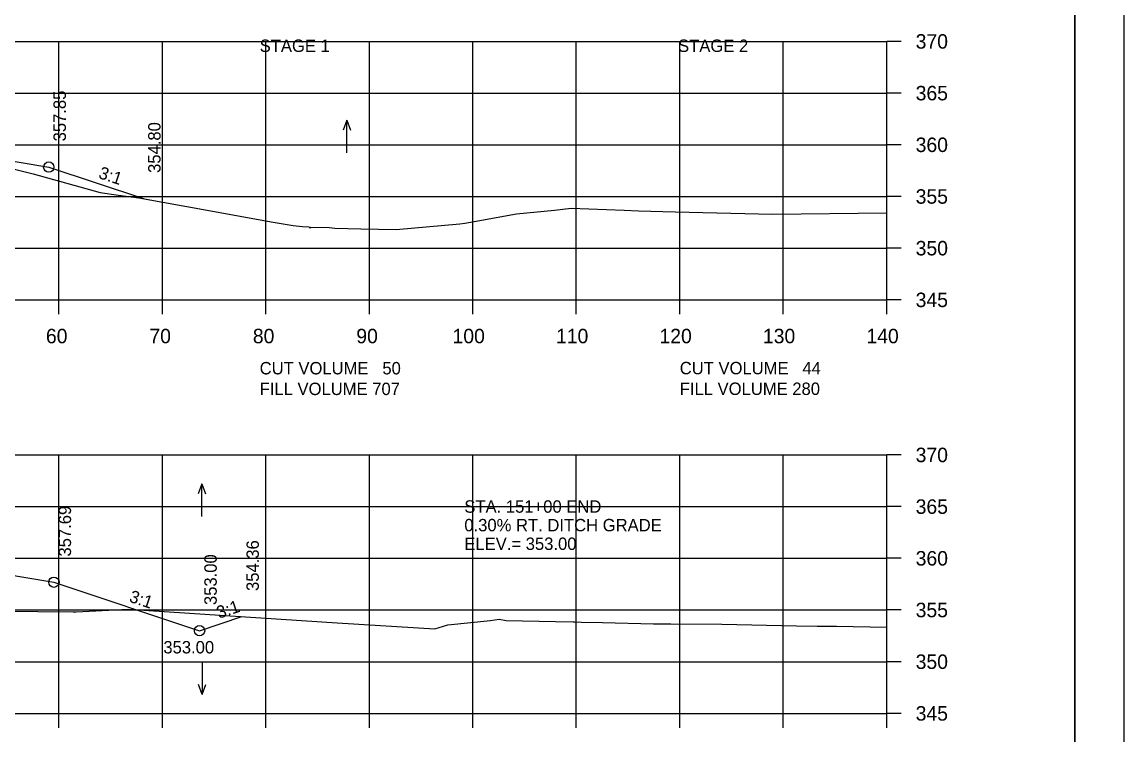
# Model space of a CAD drawing. Extents: x 1374859 to 1376773, y 382242 to 389804.
# Drawn here: x 1376191 to 1376297.5, y 386606.4 to 386675.4 of the extents above; entities that cross this region are included whole.
import ezdxf

# ---------------------------------------------------------------- set-up
doc = ezdxf.new("R2010")
doc.units = 0
for name, color, linetype in [('R_Axis', 7, 'Continuous'), ('R_Axis Annot', 7, 'Continuous'), ('R_Border', 7, 'Continuous'), ('R_Detour Annot', 7, 'Continuous'), ('R_Exist Surface', 7, 'Continuous'), ('R_Fin Surface', 7, 'Continuous'), ('R_Grid', 7, 'Continuous'), ('R_No Plot', 7, 'Continuous'), ('R_Water Annot', 7, 'Continuous'), ('R_Xsect Elev', 7, 'Continuous'), ('R_Xsect Slope', 7, 'Continuous')]:
    doc.layers.add(name, color=color, linetype=linetype)

msp = doc.modelspace()

# ---------------------------------------------------------------- linework, layer by layer
at = {"layer": 'R_Axis'}
for p, q in [((1376274.57, 386648.48), (1376274.57, 386673.48)), ((1376275.97, 386673.48), (1376274.57, 386673.48)), ((1376275.97, 386668.48), (1376274.57, 386668.48)), ((1376275.97, 386663.48), (1376274.57, 386663.48)), ((1376275.97, 386658.48), (1376274.57, 386658.48)), ((1376275.97, 386653.48), (1376274.57, 386653.48)), ((1375994.57, 386648.48), (1376274.57, 386648.48)), ((1376194.57, 386647.08), (1376194.57, 386648.48)), ((1376204.57, 386647.08), (1376204.57, 386648.48)), ((1376214.57, 386647.08), (1376214.57, 386648.48)), ((1376224.57, 386647.08), (1376224.57, 386648.48)), ((1376234.57, 386647.08), (1376234.57, 386648.48)), ((1376244.57, 386647.08), (1376244.57, 386648.48)), ((1376254.57, 386647.08), (1376254.57, 386648.48)), ((1376264.57, 386647.08), (1376264.57, 386648.48)), ((1376274.57, 386647.08), (1376274.57, 386648.48)), ((1376275.97, 386648.48), (1376274.57, 386648.48)), ((1376274.57, 386608.48), (1376274.57, 386633.48)), ((1376275.97, 386633.48), (1376274.57, 386633.48)), ((1376275.97, 386628.48), (1376274.57, 386628.48)), ((1376275.97, 386623.48), (1376274.57, 386623.48)), ((1376275.97, 386618.48), (1376274.57, 386618.48)), ((1376275.97, 386613.48), (1376274.57, 386613.48)), ((1375994.57, 386608.48), (1376274.57, 386608.48)), ((1376194.57, 386607.08), (1376194.57, 386608.48)), ((1376204.57, 386607.08), (1376204.57, 386608.48)), ((1376214.57, 386607.08), (1376214.57, 386608.48)), ((1376224.57, 386607.08), (1376224.57, 386608.48)), ((1376234.57, 386607.08), (1376234.57, 386608.48)), ((1376244.57, 386607.08), (1376244.57, 386608.48)), ((1376254.57, 386607.08), (1376254.57, 386608.48)), ((1376264.57, 386607.08), (1376264.57, 386608.48)), ((1376274.57, 386607.08), (1376274.57, 386608.48)), ((1376275.97, 386608.48), (1376274.57, 386608.48))]:
    msp.add_line(p, q, dxfattribs=at)
at = {"layer": 'R_Border'}
msp.add_line((1376292.75, 386512.48), (1376292.75, 386717.94), dxfattribs=at)
at = {"layer": 'R_Exist Surface'}
for points in [[(1376190.27, 386661.12), (1376192.09, 386660.68), (1376198.56, 386658.87), (1376200.32, 386658.61), (1376202.29, 386658.36), (1376209.25, 386657.09), (1376215.09, 386656.03), (1376217.22, 386655.66), (1376218.1, 386655.56), (1376218.71, 386655.53), (1376218.84, 386655.43), (1376218.93, 386655.52), (1376220.72, 386655.47), (1376221.23, 386655.4), (1376223.74, 386655.34), (1376227.16, 386655.28), (1376233.31, 386655.84), (1376233.8, 386655.89), (1376234.34, 386655.99), (1376238.78, 386656.8), (1376242.46, 386657.17), (1376244.07, 386657.34), (1376249.19, 386657.17), (1376250.58, 386657.1), (1376254.12, 386657.01), (1376263.54, 386656.76), (1376274.57, 386656.91)], [(1376189.12, 386618.37), (1376195.93, 386618.29), (1376196.15, 386618.29), (1376196.2, 386618.29), (1376196.21, 386618.29), (1376196.21, 386618.3), (1376196.22, 386618.3), (1376201.3, 386618.56), (1376221.45, 386617.23), (1376230.9, 386616.66), (1376232.16, 386617.03), (1376236.29, 386617.45), (1376237.13, 386617.6), (1376237.8, 386617.48), (1376242.55, 386617.37), (1376244.28, 386617.33), (1376244.41, 386617.35), (1376245.07, 386617.31), (1376247.09, 386617.27), (1376252.03, 386617.13), (1376253.72, 386617.15), (1376258.63, 386617.11), (1376265.84, 386616.95), (1376267.85, 386616.93), (1376269.73, 386616.92), (1376274.57, 386616.82)]]:
    msp.add_lwpolyline(points, dxfattribs=at)
at = {"layer": 'R_Fin Surface'}
for points in [[(1376053.96, 386656.68), (1376057.81, 386655.4), (1376075.59, 386661.33), (1376090.15, 386663.76), (1376097.59, 386665), (1376105.59, 386665.32), (1376134.59, 386665.9), (1376163.59, 386665.32), (1376171.59, 386665), (1376179.02, 386663.76), (1376193.59, 386661.33), (1376202.74, 386658.28)], [(1376052.47, 386616.79), (1376057.21, 386615.21), (1376075.09, 386621.17), (1376089.65, 386623.6), (1376097.09, 386624.84), (1376105.09, 386625.16), (1376134.59, 386625.75), (1376164.09, 386625.16), (1376172.09, 386624.84), (1376179.52, 386623.6), (1376194.09, 386621.17), (1376208.16, 386616.48), (1376212.24, 386617.84)]]:
    msp.add_lwpolyline(points, dxfattribs=at)
at = {"layer": 'R_Grid'}
for p, q in [((1375994.57, 386673.48), (1376274.57, 386673.48)), ((1376194.57, 386648.48), (1376194.57, 386673.48)), ((1376204.57, 386648.48), (1376204.57, 386673.48)), ((1376214.57, 386648.48), (1376214.57, 386673.48)), ((1376224.57, 386648.48), (1376224.57, 386673.48)), ((1376234.57, 386648.48), (1376234.57, 386673.48)), ((1376244.57, 386648.48), (1376244.57, 386673.48)), ((1376254.57, 386648.48), (1376254.57, 386673.48)), ((1376264.57, 386648.48), (1376264.57, 386673.48)), ((1376274.57, 386648.48), (1376274.57, 386673.48)), ((1375994.57, 386668.48), (1376274.57, 386668.48)), ((1375994.57, 386663.48), (1376274.57, 386663.48)), ((1375994.57, 386658.48), (1376274.57, 386658.48)), ((1375994.57, 386653.48), (1376274.57, 386653.48)), ((1375994.57, 386648.48), (1376274.57, 386648.48)), ((1375994.57, 386633.48), (1376274.57, 386633.48)), ((1376194.57, 386608.48), (1376194.57, 386633.48)), ((1376204.57, 386608.48), (1376204.57, 386633.48)), ((1376214.57, 386608.48), (1376214.57, 386633.48)), ((1376224.57, 386608.48), (1376224.57, 386633.48)), ((1376234.57, 386608.48), (1376234.57, 386633.48)), ((1376244.57, 386608.48), (1376244.57, 386633.48)), ((1376254.57, 386608.48), (1376254.57, 386633.48)), ((1376264.57, 386608.48), (1376264.57, 386633.48)), ((1376274.57, 386608.48), (1376274.57, 386633.48)), ((1375994.57, 386628.48), (1376274.57, 386628.48)), ((1375994.57, 386623.48), (1376274.57, 386623.48)), ((1375994.57, 386618.48), (1376274.57, 386618.48)), ((1375994.57, 386613.48), (1376274.57, 386613.48)), ((1375994.57, 386608.48), (1376274.57, 386608.48))]:
    msp.add_line(p, q, dxfattribs=at)
at = {"layer": 'R_No Plot'}
for points in [[(1375964.16, 386721.83), (1376297.5, 386721.83), (1376297.5, 386508.5), (1375964.16, 386508.5)], [(1376210.49, 386717.94), (1376210.49, 386708.06), (1376246.22, 386708.06), (1376246.22, 386705.14), (1376269.42, 386705.14), (1376269.42, 386680.81), (1376292.75, 386680.81), (1376292.75, 386512.48), (1375976.57, 386512.48), (1375976.57, 386717.94)]]:
    msp.add_lwpolyline(points, close=True, dxfattribs=at)
for centre in [(1376193.59, 386661.33), (1376194.09, 386621.17), (1376208.16, 386616.48)]:
    msp.add_circle(centre, 0.5, dxfattribs=at)
at = {"layer": 'R_Water Annot'}
for p, q in [((1376222.4, 386665.85), (1376222.05, 386664.89)), ((1376222.4, 386662.71), (1376222.4, 386665.85)), ((1376222.4, 386665.85), (1376222.75, 386664.89)), ((1376208.37, 386630.68), (1376208.02, 386629.72)), ((1376208.37, 386627.54), (1376208.37, 386630.68)), ((1376208.37, 386630.68), (1376208.72, 386629.72)), ((1376208.42, 386613.45), (1376208.42, 386610.31)), ((1376208.42, 386610.31), (1376208.07, 386611.27)), ((1376208.42, 386610.31), (1376208.77, 386611.27))]:
    msp.add_line(p, q, dxfattribs=at)

# ---------------------------------------------------------------- texts
at = {"layer": 'R_Axis Annot'}
for s, p in [('STAGE 1', (1376213.97, 386672.46)), ('STAGE 2', (1376254.41, 386672.46))]:
    msp.add_text(s, height=1.2, rotation=360, dxfattribs=at).set_placement(p)
for s, height, p in [('370', 1.4, (1376277.37, 386672.78)), ('365', 1.4, (1376277.37, 386667.78)), ('360', 1.4, (1376277.37, 386662.78)), ('355', 1.4, (1376277.37, 386657.78)), ('350', 1.4, (1376277.37, 386652.78)), ('345', 1.4, (1376277.37, 386647.78)), ('60', 1.4, (1376193.31, 386644.28)), ('70', 1.4, (1376203.31, 386644.28)), ('80', 1.4, (1376213.31, 386644.28)), ('90', 1.4, (1376223.31, 386644.28)), ('100', 1.4, (1376232.61, 386644.28)), ('110', 1.4, (1376242.61, 386644.28)), ('120', 1.4, (1376252.61, 386644.28)), ('130', 1.4, (1376262.61, 386644.28)), ('140', 1.4, (1376272.61, 386644.28)), ('CUT VOLUME   50', 1.2, (1376213.97, 386641.27)), ('CUT VOLUME   44', 1.2, (1376254.57, 386641.28)), ('FILL VOLUME 707', 1.2, (1376213.97, 386639.27)), ('FILL VOLUME 280', 1.2, (1376254.57, 386639.28)), ('370', 1.4, (1376277.37, 386632.78)), ('365', 1.4, (1376277.37, 386627.78)), ('360', 1.4, (1376277.37, 386622.78)), ('355', 1.4, (1376277.37, 386617.78)), ('350', 1.4, (1376277.37, 386612.78)), ('345', 1.4, (1376277.37, 386607.78))]:
    msp.add_text(s, height=height, dxfattribs=at).set_placement(p)
at = {"layer": 'R_Detour Annot'}
for s, p in [('STA. 151+00 END', (1376233.75, 386627.89)), ('0.30% RT. DITCH GRADE', (1376233.75, 386626.09)), ('ELEV.= 353.00', (1376233.75, 386624.29))]:
    msp.add_text(s, height=1.2, dxfattribs=at).set_placement(p)
at = {"layer": 'R_Xsect Elev'}
for s, p in [('357.85', (1376195.24, 386663.81)), ('354.80', (1376204.39, 386660.76)), ('357.69', (1376195.74, 386623.65)), ('354.36', (1376213.89, 386620.32)), ('353.00', (1376209.82, 386618.96))]:
    msp.add_text(s, height=1.2, rotation=90, dxfattribs=at).set_placement(p)
msp.add_text('353.00', height=1.2, dxfattribs=at).set_placement((1376204.66, 386614.28))
at = {"layer": 'R_Xsect Slope'}
for rotation, p in [(341.5651, (1376198.32, 386660.28)), (341.5651, (1376201.28, 386619.3)), (18.4349, (1376210.04, 386617.63))]:
    msp.add_text('3:1', height=1.2, rotation=rotation, dxfattribs=at).set_placement(p)

doc.saveas('drawing.dxf')
